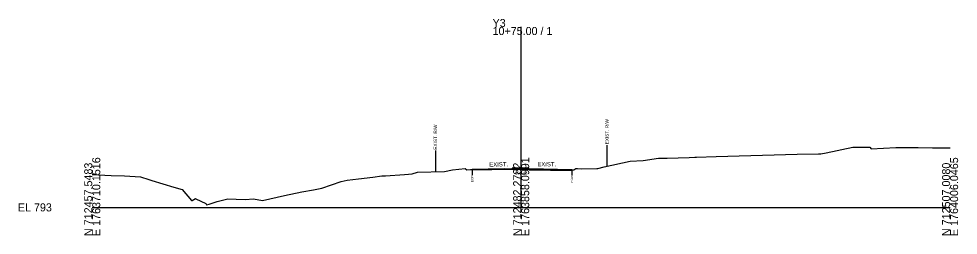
# Model space of a CAD drawing. Extents: x -26 to 2903, y -10 to 5022.
# Drawn here: x 2574.3 to 2902.8, y -9.7 to 65.8 of the extents above; entities that cross this region are included whole.
import ezdxf

# ---------------------------------------------------------------- set-up
doc = ezdxf.new("R2010")
doc.units = 0
for name, color, linetype in [('Exist Cross Section Cell', 7, 'Continuous'), ('Exist XS Center Line Elevation Label', 7, 'Continuous'), ('Exist XS Ground Line', 7, 'Continuous'), ('Old_Level_10', 7, 'Continuous'), ('Prop CMT Pvmt Course 1', 7, 'Continuous'), ('Prop CMT Pvmt Surface', 7, 'Continuous'), ('Prop XS Conc Monolithic Island', 7, 'Continuous'), ('Prop XS Earthwork Shape', 7, 'Continuous'), ('Prop XS SE Text', 7, 'Continuous')]:
    doc.layers.add(name, color=color, linetype=linetype)

msp = doc.modelspace()

# ---------------------------------------------------------------- linework, layer by layer
at = {"layer": 'Exist Cross Section Cell'}
for p, q in [((2750, 0), (2750, 62.95)), ((2600, 0), (2750, 0)), ((2750, 0), (2900, 0))]:
    msp.add_line(p, q, dxfattribs=at)
at = {"layer": 'Exist XS Ground Line'}
msp.add_lwpolyline([(2600, 11.47), (2606.67, 11.07), (2611.32, 10.98), (2616.85, 10.65), (2619.78, 9.79), (2620.83, 9.4), (2628.53, 7.09), (2631.43, 6.25), (2634.74, 2.38), (2634.89, 2.45), (2636.11, 3.15), (2636.25, 2.98), (2639.71, 1.39), (2640, 0.85), (2640.84, 1.16), (2643.68, 2.05), (2647.41, 3.01), (2650.33, 2.84), (2653.44, 2.74), (2656.38, 2.96), (2659.52, 2.36), (2667.22, 4.18), (2673.34, 5.42), (2677.36, 6.18), (2680.27, 6.76), (2687.03, 9.07), (2689.17, 9.49), (2693.16, 9.95), (2698.07, 10.6), (2701.28, 10.96), (2702.59, 11.04), (2709.17, 11.53), (2710.57, 11.61), (2711.93, 11.73), (2713.78, 12.26), (2723.13, 12.49), (2725.96, 13.05), (2730.41, 13.52), (2731.03, 13.14), (2732.27, 13.23), (2732.88, 13.27), (2736.61, 13.34), (2744.02, 13.45), (2750, 13.42), (2751.59, 13.41), (2755.78, 13.4), (2762.87, 13.27), (2766.6, 13.17), (2767.77, 13.15), (2768.4, 13.12), (2769.12, 13.54), (2769.65, 13.56), (2770.99, 13.47), (2776.5, 13.54), (2776.84, 13.55), (2778.97, 14.11), (2788.13, 16.1), (2792.66, 16.37), (2798, 17.23), (2799.87, 17.22), (2801.01, 17.22), (2808.72, 17.42), (2810.75, 17.47), (2811.28, 17.48), (2818.21, 17.72), (2846.53, 18.56), (2853.98, 18.7), (2854.76, 18.68), (2856.69, 19.06), (2865.98, 20.98), (2869.29, 20.98), (2871.98, 20.98), (2872.39, 20.48), (2881.08, 20.84), (2883.71, 20.9), (2888.78, 20.85), (2893.85, 20.82), (2897.47, 20.79), (2900, 20.78)], dxfattribs=at)
at = {"layer": 'Old_Level_10'}
for p, q in [((2720, 19.82), (2720, 12.41)), ((2780, 21.73), (2780, 14.33)), ((2732.88, 13.27), (2732.88, 11.22)), ((2767.77, 13.15), (2767.77, 11.1))]:
    msp.add_line(p, q, dxfattribs=at)
at = {"layer": 'Prop CMT Pvmt Course 1'}
for points in [[(2744.02, 13.45), (2732.88, 13.27)], [(2746.68, 13.18), (2732.88, 13.02)], [(2750, 13.16), (2750, 13.16), (2750, 13.16)], [(2751.93, 13.14), (2751.93, 13.14), (2751.93, 13.14)], [(2752.76, 13.4), (2767.77, 13.15)], [(2752.76, 13.15), (2767.77, 12.9)]]:
    msp.add_lwpolyline(points, dxfattribs=at)
at = {"layer": 'Prop CMT Pvmt Surface'}
for points in [[(2746.68, 13.43), (2732.88, 13.27)], [(2752.76, 13.4), (2767.77, 13.15)]]:
    msp.add_lwpolyline(points, dxfattribs=at)
at = {"layer": 'Prop XS Conc Monolithic Island'}
for p, q in [((2746.68, 13.43), (2747.03, 13.8)), ((2746.68, 13.18), (2746.68, 13.43)), ((2752.76, 13.15), (2746.68, 13.18)), ((2747.15, 13.85), (2752.29, 13.82)), ((2752.76, 13.4), (2752.41, 13.77)), ((2752.76, 13.15), (2752.76, 13.4))]:
    msp.add_line(p, q, dxfattribs=at)
for centre, start, end in [((2747.15, 13.68), 90, 135.9991), ((2752.29, 13.65), 44.0009, 90)]:
    msp.add_arc(centre, 0.167, start, end, dxfattribs=at)
at = {"layer": 'Prop XS Earthwork Shape'}
for points in [[(2732.88, 13.27), (2736.61, 13.34), (2744.02, 13.45), (2746.68, 13.43)], [(2755.78, 13.4), (2762.87, 13.27), (2766.6, 13.17), (2767.77, 13.15), (2752.76, 13.4)]]:
    msp.add_lwpolyline(points, close=True, dxfattribs=at)

# ---------------------------------------------------------------- texts
at = {"layer": 'Exist Cross Section Cell'}
for s, p in [('Y3', (2740, 62.95)), ('10+75.00 / 1', (2740, 60.15)), ('EL 793', (2574, -1.4))]:
    msp.add_text(s, height=2.8, dxfattribs=at).set_placement(p)
for s, p in [('E 1763710.1516', (2602.8, -10)), ('E 1763858.0991', (2752.8, -10)), ('E 1764006.0465', (2902.8, -10)), ('N 712457.5483', (2600, -10)), ('N 712482.2782', (2750, -10)), ('N 712507.0080', (2900, -10))]:
    msp.add_text(s, height=2.8, rotation=90, dxfattribs=at).set_placement(p)
at = {"layer": 'Exist XS Center Line Elevation Label'}
msp.add_text('806.42', height=1, dxfattribs=at).set_placement((2747.89, 11.42))
at = {"layer": 'Old_Level_10'}
for s, height, p in [('EXIST. R/W', 1.181, (2780.59, 22.03)), ('EXIST. R/W', 1.181, (2720.59, 20.12)), ('EOP', 0.787, (2733.27, 8.82)), ('EOP', 0.787, (2768.16, 8.7))]:
    msp.add_text(s, height=height, rotation=90, dxfattribs=at).set_placement(p)
at = {"layer": 'Prop XS SE Text'}
for rotation, p in [(1.0599, (2738.87, 14.21)), (359.513, (2755.66, 14.36))]:
    msp.add_text('EXIST.', height=1.5, rotation=rotation, dxfattribs=at).set_placement(p)

doc.saveas('drawing.dxf')
